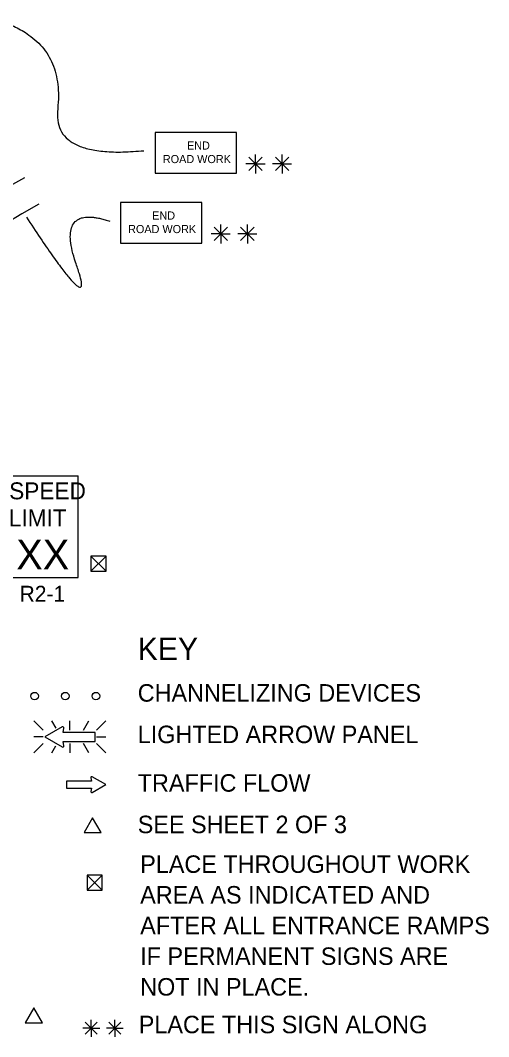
# Model space of a CAD drawing. Extents: x 16715 to 19504, y 7040 to 8495.
# Drawn here: x 17179 to 17428, y 7607 to 8147 of the extents above; entities that cross this region are included whole.
import ezdxf

# ---------------------------------------------------------------- set-up
doc = ezdxf.new("R2010")
doc.units = 0
for name, color, linetype in [('MT_SCRATCH_LEVEL_E', 7, 'Continuous'), ('PAVT_EDGE_EX', 7, 'Continuous'), ('TRAFFIC_SIGNS_PR', 7, 'Continuous'), ('TYPICAL_TEXT_DIMEN_EX', 7, 'Continuous'), ('TYPICAL_TEXT_DIMEN_PR', 7, 'Continuous')]:
    doc.layers.add(name, color=color, linetype=linetype)

msp = doc.modelspace()

# ---------------------------------------------------------------- linework, layer by layer
at = {"layer": 'MT_SCRATCH_LEVEL_E'}
for p, q in [((17216.4, 7742.81), (17203.14, 7742.81)), ((17203.14, 7742.81), (17203.14, 7739.07)), ((17216.08, 7744.59), (17216.4, 7742.81)), ((17224.01, 7740.96), (17216.77, 7745.07)), ((17216.77, 7736.81), (17224.01, 7740.96)), ((17203.14, 7739.07), (17216.4, 7739.07)), ((17216.4, 7739.07), (17216.08, 7737.29))]:
    msp.add_line(p, q, dxfattribs=at)
for centre, start, end in [((17216.54, 7744.66), 60.4248, 189.9638), ((17216.54, 7737.22), 170.0362, 299.7731)]:
    msp.add_arc(centre, 0.463, start, end, dxfattribs=at)
at = {"layer": 'PAVT_EDGE_EX'}
for radius in [316, 300]:
    msp.add_arc((17331.24, 7785.52), radius, 118.4372, 180, dxfattribs=at)
at = {"layer": 'TRAFFIC_SIGNS_PR'}
for p, q in [((17166.19, 7905.08), (17209.39, 7905.08)), ((17209.39, 7851.08), (17209.39, 7905.08)), ((17166.19, 7851.08), (17209.39, 7851.08)), ((17185.86, 7774.77), (17190.79, 7769.83)), ((17197.62, 7770.94), (17195.42, 7774.77)), ((17204.94, 7769.83), (17204.94, 7774.77)), ((17212.18, 7769.83), (17215.03, 7774.77)), ((17219.09, 7769.83), (17224.03, 7774.77)), ((17190.79, 7766.28), (17185.86, 7766.28)), ((17185.86, 7757.79), (17190.79, 7762.72)), ((17204.94, 7762.72), (17204.94, 7757.79)), ((17215.07, 7757.79), (17212.22, 7762.72)), ((17219.09, 7766.28), (17224.03, 7766.28)), ((17219.09, 7762.72), (17224.03, 7757.78)), ((17195.37, 7757.79), (17197.48, 7761.45))]:
    msp.add_line(p, q, dxfattribs=at)
for points in [[(17250.34, 8065.88), (17293.54, 8065.88), (17293.54, 8087.48), (17250.34, 8087.48)], [(17231.86, 8028.68), (17275.06, 8028.68), (17275.06, 8050.28), (17231.86, 8050.28)]]:
    msp.add_lwpolyline(points, close=True, dxfattribs=at)
for points in [[(17200.87, 7771.55), (17191.58, 7766.28), (17200.87, 7760.96)], [(17201.74, 7761.59), (17201.34, 7763.85), (17218.36, 7763.85), (17218.36, 7768.65), (17201.34, 7768.65), (17201.75, 7770.94)]]:
    msp.add_lwpolyline(points, dxfattribs=at)
for centre in [(17186.2, 7787.96), (17202.5, 7787.96), (17218.8, 7787.96)]:
    msp.add_circle(centre, 2, dxfattribs=at)
for centre, radius, start, end in [((17201.16, 7771.03), 0.598, 350.7308, 118.8916), ((17201.16, 7761.48), 0.597, 241.4833, 9.9593)]:
    msp.add_arc(centre, radius, start, end, dxfattribs=at)
at = {"layer": 'TYPICAL_TEXT_DIMEN_PR'}
for p, q in [((17303.69, 8070.8), (17303.69, 8075.82)), ((17317.82, 8070.8), (17317.82, 8075.82)), ((17303.69, 8070.8), (17298.59, 8070.8)), ((17307.28, 8074.39), (17300.1, 8067.22)), ((17300.11, 8074.39), (17307.28, 8067.22)), ((17303.69, 8070.8), (17307.28, 8070.8)), ((17303.69, 8070.8), (17308.73, 8070.8)), ((17303.69, 8070.8), (17303.69, 8065.74)), ((17317.82, 8070.8), (17312.72, 8070.8)), ((17314.23, 8074.39), (17321.4, 8067.22)), ((17321.4, 8074.39), (17314.23, 8067.22)), ((17317.82, 8070.8), (17321.4, 8070.8)), ((17317.82, 8070.8), (17322.85, 8070.8)), ((17317.82, 8070.8), (17317.82, 8065.74)), ((17288.8, 8037.19), (17281.62, 8030.02)), ((17281.63, 8037.19), (17288.8, 8030.02)), ((17285.21, 8033.6), (17285.21, 8038.61)), ((17295.75, 8037.19), (17302.92, 8030.02)), ((17302.92, 8037.19), (17295.75, 8030.02)), ((17299.34, 8033.6), (17299.34, 8038.61)), ((17285.21, 8033.6), (17280.11, 8033.6)), ((17285.21, 8033.6), (17288.8, 8033.6)), ((17285.21, 8033.6), (17290.25, 8033.6)), ((17285.21, 8033.6), (17285.21, 8028.54)), ((17299.34, 8033.6), (17294.24, 8033.6)), ((17299.34, 8033.6), (17302.92, 8033.6)), ((17299.34, 8033.6), (17304.37, 8033.6)), ((17299.34, 8033.6), (17299.34, 8028.54)), ((17216.18, 7862.4), (17224.18, 7854.4)), ((17216.18, 7854.4), (17224.18, 7862.4)), ((17214.18, 7692.76), (17222.18, 7684.76)), ((17214.18, 7684.76), (17222.18, 7692.76)), ((17216.33, 7611.47), (17216.33, 7615.93)), ((17228.88, 7611.47), (17228.88, 7615.93)), ((17216.33, 7611.47), (17211.79, 7611.47)), ((17213.14, 7614.66), (17219.51, 7608.28)), ((17219.51, 7614.66), (17213.14, 7608.28)), ((17216.33, 7611.47), (17219.51, 7611.47)), ((17216.33, 7611.47), (17220.8, 7611.47)), ((17216.33, 7611.47), (17216.33, 7606.97)), ((17228.88, 7611.47), (17224.35, 7611.47)), ((17232.07, 7614.66), (17225.69, 7608.28)), ((17225.7, 7614.66), (17232.07, 7608.28)), ((17228.88, 7611.47), (17232.07, 7611.47)), ((17228.88, 7611.47), (17233.36, 7611.47)), ((17228.88, 7611.47), (17228.88, 7606.97))]:
    msp.add_line(p, q, dxfattribs=at)
for points in [[(17216.18, 7862.4), (17216.18, 7854.4), (17224.18, 7854.4), (17224.18, 7862.4)], [(17217.07, 7723.25), (17212.55, 7715.41), (17221.6, 7715.41)], [(17214.18, 7692.76), (17214.18, 7684.76), (17222.18, 7684.76), (17222.18, 7692.76)], [(17185.78, 7622.24), (17181.26, 7614.41), (17190.31, 7614.41)]]:
    msp.add_lwpolyline(points, close=True, dxfattribs=at)
for points in [[(17140.6, 8119.52), (17134.59, 8139.51), (17167.51, 8151.04), (17201.36, 8125.68), (17195.57, 8073.25), (17244.37, 8077.78)], [(17181.86, 8042.42), (17220.09, 7984.24), (17196.88, 8049.95), (17226.24, 8040.37)]]:
    msp.add_open_spline(points, degree=2, dxfattribs=at)

# ---------------------------------------------------------------- texts
at = {"layer": 'TRAFFIC_SIGNS_PR'}
for s, height, p in [('END', 4.31, (17267.22, 8078.4)), ('ROAD WORK', 4.31, (17254.4, 8071.22)), ('END', 4.31, (17248.74, 8041.2)), ('ROAD WORK', 4.31, (17235.92, 8034.02)), ('SPEED', 9, (17172.68, 7892.55)), ('LIMIT', 9, (17172.5, 7878.15)), ('XX', 15.785, (17176.45, 7855.3)), ('R2-1', 8.37, (17178.2, 7838.21))]:
    msp.add_text(s, height=height, dxfattribs=at).set_placement(p)
at = {"layer": 'TYPICAL_TEXT_DIMEN_EX'}
for s, height, p in [('KEY', 12, (17241.04, 7807.07)), ('CHANNELIZING DEVICES', 9.3, (17241.04, 7785.02)), ('LIGHTED ARROW PANEL', 9.3, (17241.04, 7762.97)), ('TRAFFIC FLOW', 9.3, (17241.04, 7737.17)), ('SEE SHEET 2 OF 3', 9.3, (17241.04, 7715.12)), ('PLACE THROUGHOUT WORK', 9.3, (17242.36, 7694.01)), ('AREA AS INDICATED AND', 9.3, (17242.36, 7677.71)), ('AFTER ALL ENTRANCE RAMPS', 9.3, (17242.36, 7661.41)), ('IF PERMANENT SIGNS ARE', 9.3, (17242.36, 7645.11)), ('NOT IN PLACE.', 9.3, (17242.36, 7628.81)), ('PLACE THIS SIGN ALONG', 9.3, (17241.59, 7608.79))]:
    msp.add_text(s, height=height, dxfattribs=at).set_placement(p)

doc.saveas('drawing.dxf')
